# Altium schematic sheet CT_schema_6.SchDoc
size 479 x 328 mm
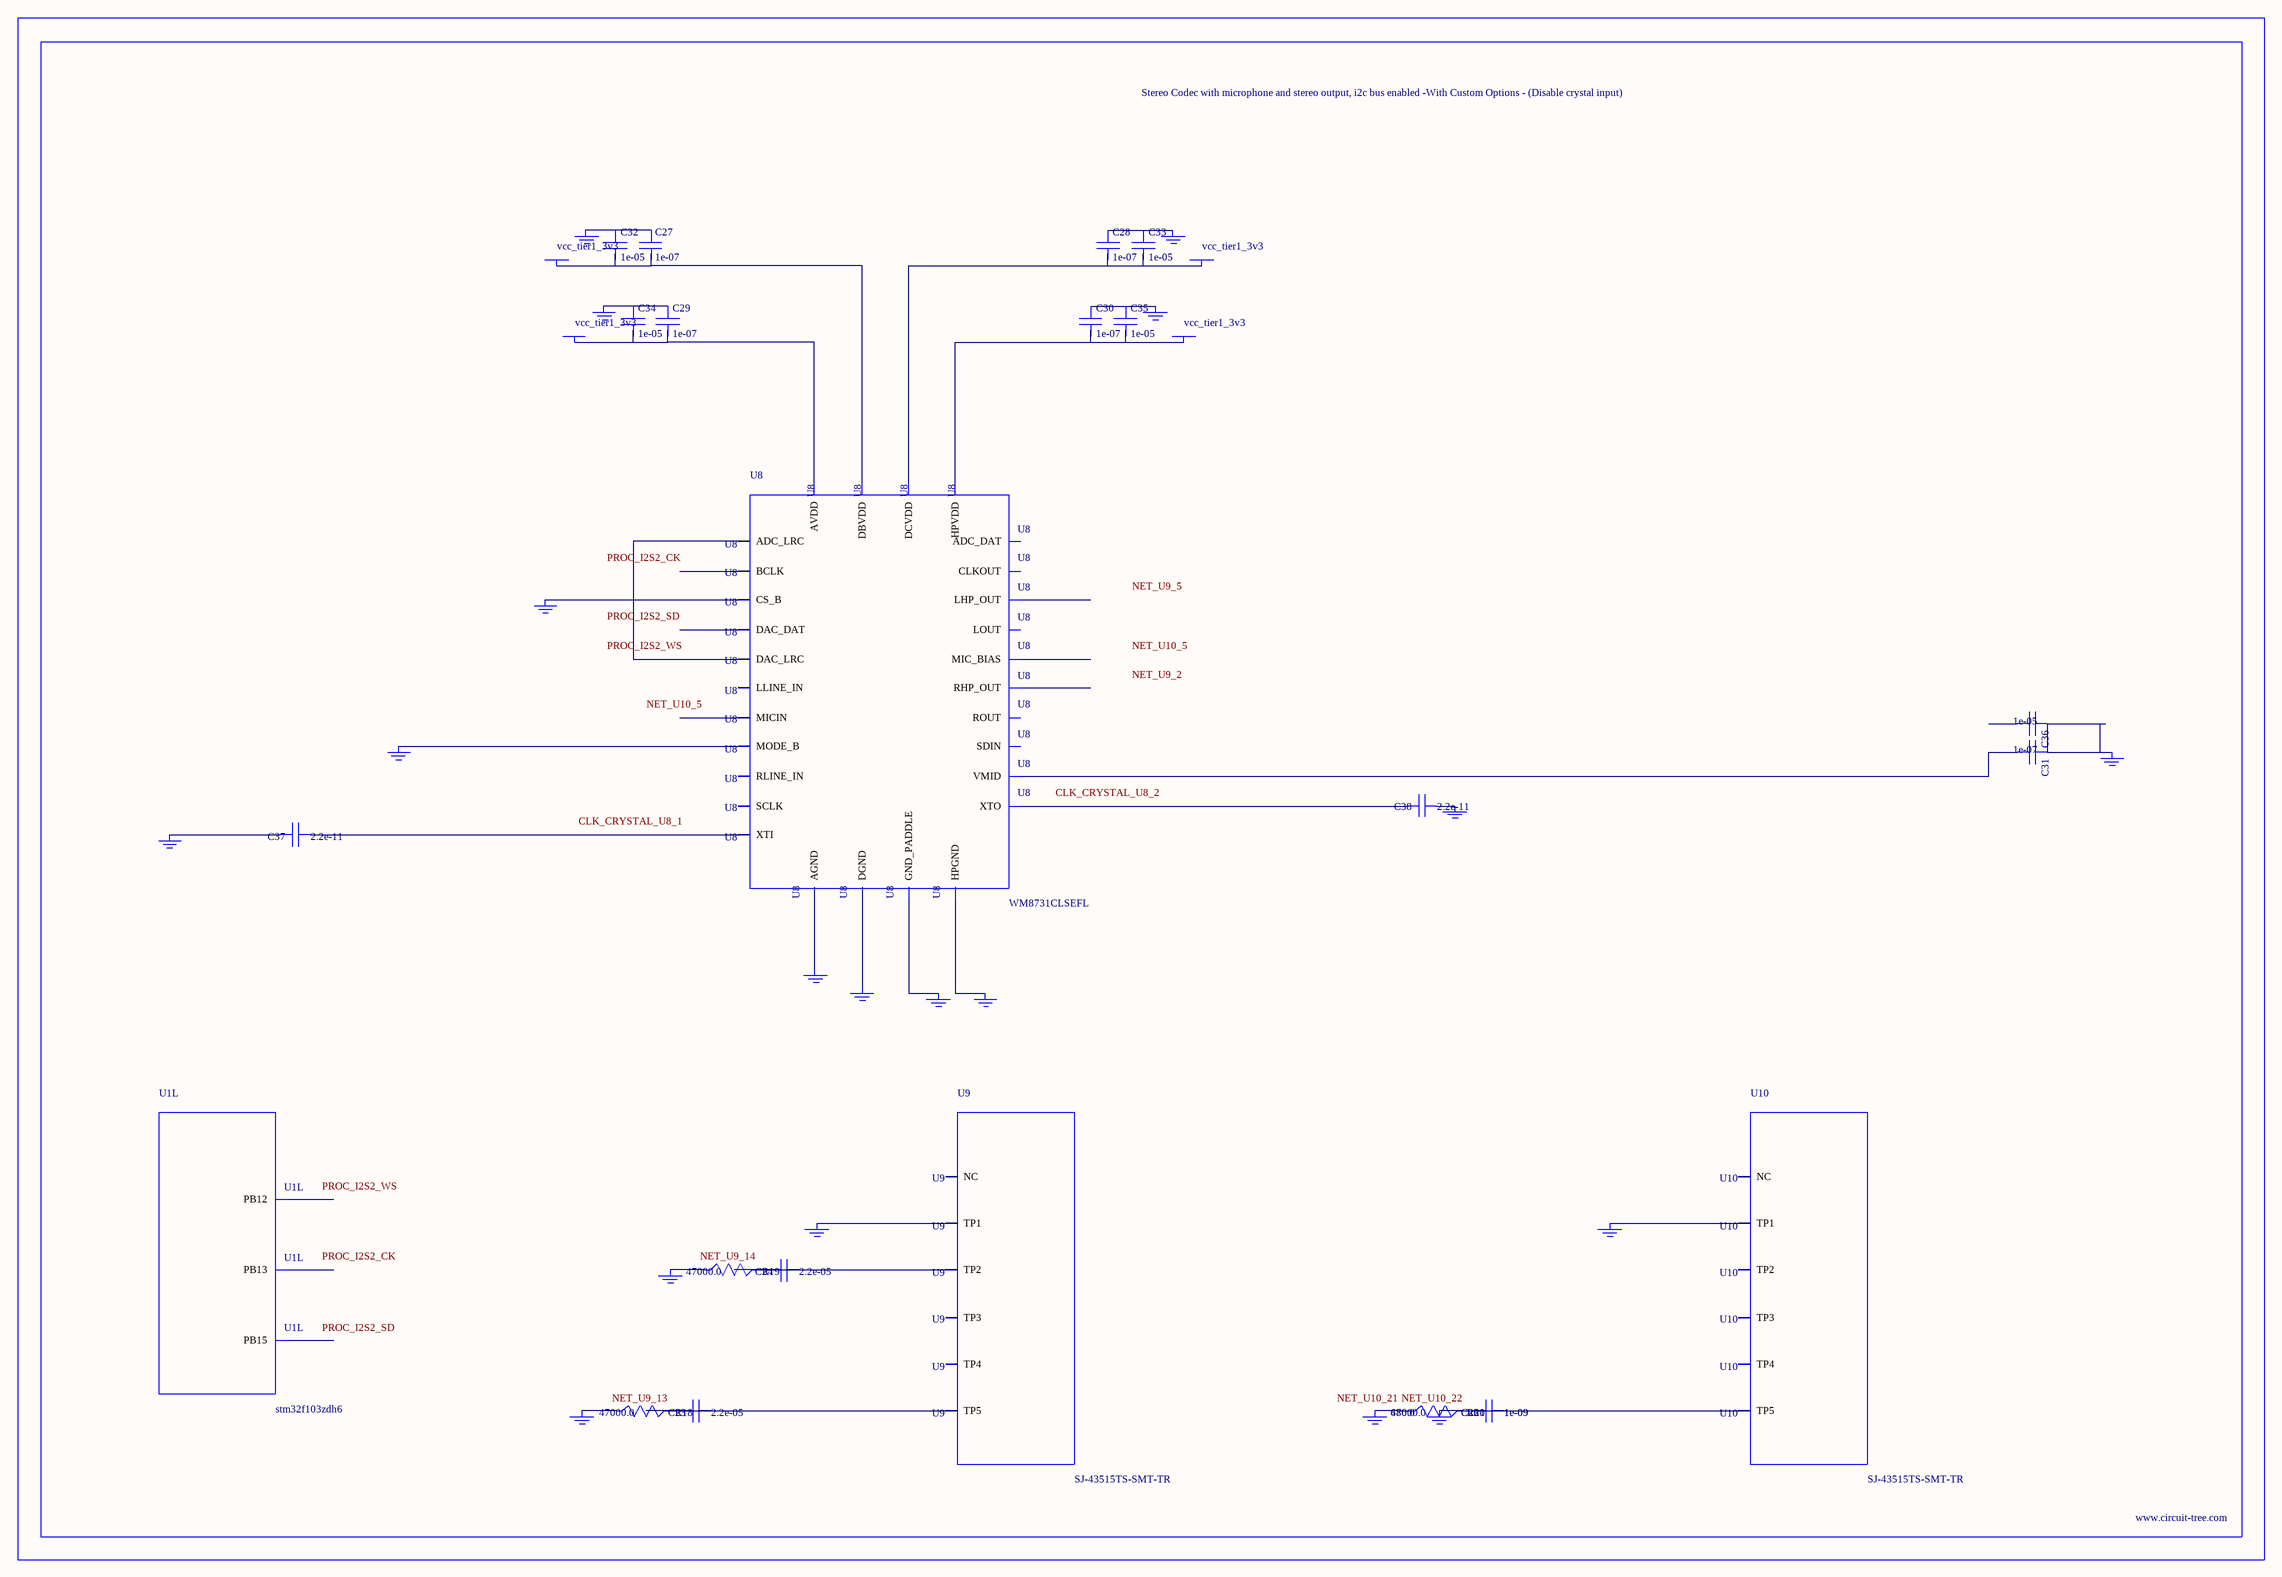
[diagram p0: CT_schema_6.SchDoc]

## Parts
BORDER5  (no value)
C23  2.2e-05  [C1210]
C24  2.2e-05  [C1210]
C25  1e-09  [C0402]
C26  1e-09  [C0402]
C27  1e-07  [C0402]
C28  1e-07  [C0402]
C29  1e-07  [C0402]
C30  1e-07  [C0402]
C31  1e-07  [C0402]
C32  1e-05  [C0805]
C33  1e-05  [C0805]
C34  1e-05  [C0805]
C35  1e-05  [C0805]
C36  1e-05  [C0805]
C37  2.2e-11  [C0402]
C38  2.2e-11  [C0402]
GND_INSTANCE_5_0  (no value)
GND_INSTANCE_5_1  (no value)
GND_INSTANCE_5_2  (no value)
GND_INSTANCE_5_3  (no value)
GND_INSTANCE_5_4  (no value)
GND_INSTANCE_5_5  (no value)
GND_INSTANCE_5_6  (no value)
GND_INSTANCE_5_7  (no value)
GND_INSTANCE_5_8  (no value)
GND_INSTANCE_5_9  (no value)
GND_INSTANCE_5_10  (no value)
GND_INSTANCE_5_11  (no value)
GND_INSTANCE_5_12  (no value)
GND_INSTANCE_5_13  (no value)
GND_INSTANCE_5_14  (no value)
GND_INSTANCE_5_15  (no value)
GND_INSTANCE_5_16  (no value)
GND_INSTANCE_5_17  (no value)
GND_INSTANCE_5_18  (no value)
POWER_INSTANCE_5_0  vcc_tier1_3v3
POWER_INSTANCE_5_1  vcc_tier1_3v3
POWER_INSTANCE_5_2  vcc_tier1_3v3
POWER_INSTANCE_5_3  vcc_tier1_3v3
R18  47000.0  [R0603]
R19  47000.0  [R0603]
R20  47000.0  [R0603]
R21  680.0  [R0603]
U1  stm32f103zdh6  [LFBGA144]  (part L of 12)
U8  WM8731CLSEFL  [QFN-28]
U9  SJ-43515TS-SMT-TR  [SJ-43515TS-SMT-TR]
U10  SJ-43515TS-SMT-TR  [SJ-43515TS-SMT-TR]

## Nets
NetC23_1: C23.1 C23.2 R18.2 U9.5(TP5)
NetC24_1: C24.1 C24.2 R19.2 U9.2(TP2)
NetC25_1: C25.1 C25.2 C26.1 C26.2 GND_INSTANCE_5_18.0(GND) R20.2 R21.2 U10.5(TP5)
NetC27_1: C27.1 C32.1 GND_INSTANCE_5_3.0(GND)
NetC27_2: C27.2 C32.2 POWER_INSTANCE_5_1.0(PWR) U8.5(DBVDD)
NetC28_1: C28.1 C33.1 GND_INSTANCE_5_2.0(GND)
NetC28_2: C28.2 C33.2 POWER_INSTANCE_5_0.0(PWR) U8.3(DCVDD)
NetC29_1: C29.1 C34.1 GND_INSTANCE_5_6.0(GND)
NetC29_2: C29.2 C34.2 POWER_INSTANCE_5_3.0(PWR) U8.18(AVDD)
NetC30_1: C30.1 C35.1 GND_INSTANCE_5_4.0(GND)
NetC30_2: C30.2 C35.2 POWER_INSTANCE_5_2.0(PWR) U8.12(HPVDD)
NetC31_1: C31.1 C36.1 GND_INSTANCE_5_7.0(GND)
NetC31_2: C31.2 U8.20(VMID)
NetC37_1: C37.1 U8.1(XTI)
NetC37_2: C37.2 GND_INSTANCE_5_0.0(GND)
NetC38_1: C38.1 GND_INSTANCE_5_1.0(GND)
NetC38_2: C38.2 U8.2(XTO)
NetGND_INSTANCE_5_5_0: GND_INSTANCE_5_5.0(GND) U8.15(HPGND)
NetGND_INSTANCE_5_8_0: GND_INSTANCE_5_8.0(GND) U8.25(MODE_B)
NetGND_INSTANCE_5_9_0: GND_INSTANCE_5_9.0(GND) U8.26(CS_B)
NetGND_INSTANCE_5_10_0: GND_INSTANCE_5_10.0(GND) U8.29(GND_PADDLE)
NetGND_INSTANCE_5_11_0: GND_INSTANCE_5_11.0(GND) U8.4(DGND)
NetGND_INSTANCE_5_12_0: GND_INSTANCE_5_12.0(GND) U8.19(AGND)
NetGND_INSTANCE_5_13_0: GND_INSTANCE_5_13.0(GND) U9.1(TP1)
NetGND_INSTANCE_5_14_0: GND_INSTANCE_5_14.0(GND) R19.1
NetGND_INSTANCE_5_15_0: GND_INSTANCE_5_15.0(GND) R18.1
NetGND_INSTANCE_5_16_0: GND_INSTANCE_5_16.0(GND) U10.1(TP1)
NetGND_INSTANCE_5_17_0: GND_INSTANCE_5_17.0(GND) R20.1 R21.1
NetU8_9: U8.9(DAC_LRC) U8.11(ADC_LRC)

Not connected (* = marked no-connect by the designer): C36 2; U1 L12(PB15) M11(PB12) M12(PB13); U8 6(CLKOUT) 7(BCLK) 8(DAC_DAT) 10(ADC_DAT) 13(LHP_OUT) 14(RHP_OUT) 16(LOUT) 17(ROUT) 21(MIC_BIAS) 22(MICIN) 23(RLINE_IN) 24(LLINE_IN) 27(SDIN) 28(SCLK); U9 3(TP3) 4(TP4) 6(NC); U10 2(TP2) 3(TP3) 4(TP4) 6(NC)

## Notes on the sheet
- Labels drawn without touching a wire or pin: CLK_CRYSTAL_U8_1, CLK_CRYSTAL_U8_2, NET_U9_2, NET_U9_5, NET_U9_13, NET_U9_14, NET_U10_5, NET_U10_21, NET_U10_22, PROC_I2S2_CK, PROC_I2S2_SD, PROC_I2S2_WS

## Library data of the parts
BORDER5 = BORDER_PAGE5
C23 C24 = C1210C224K5RACTU
C25 C26 = C0402C102K3RAC
C27-C31 = C0402C104K3RACTU
C32-C36 = C0805C106K8RACTU
C37 C38 = C0402C220K3RAC
GND_INSTANCE_5_0-GND_INSTANCE_5_18 = GND
POWER_INSTANCE_5_0-POWER_INSTANCE_5_3 = PWR
R18-R20 = RC0603JR-0747KL
R21 = RC0603JR-07680RL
